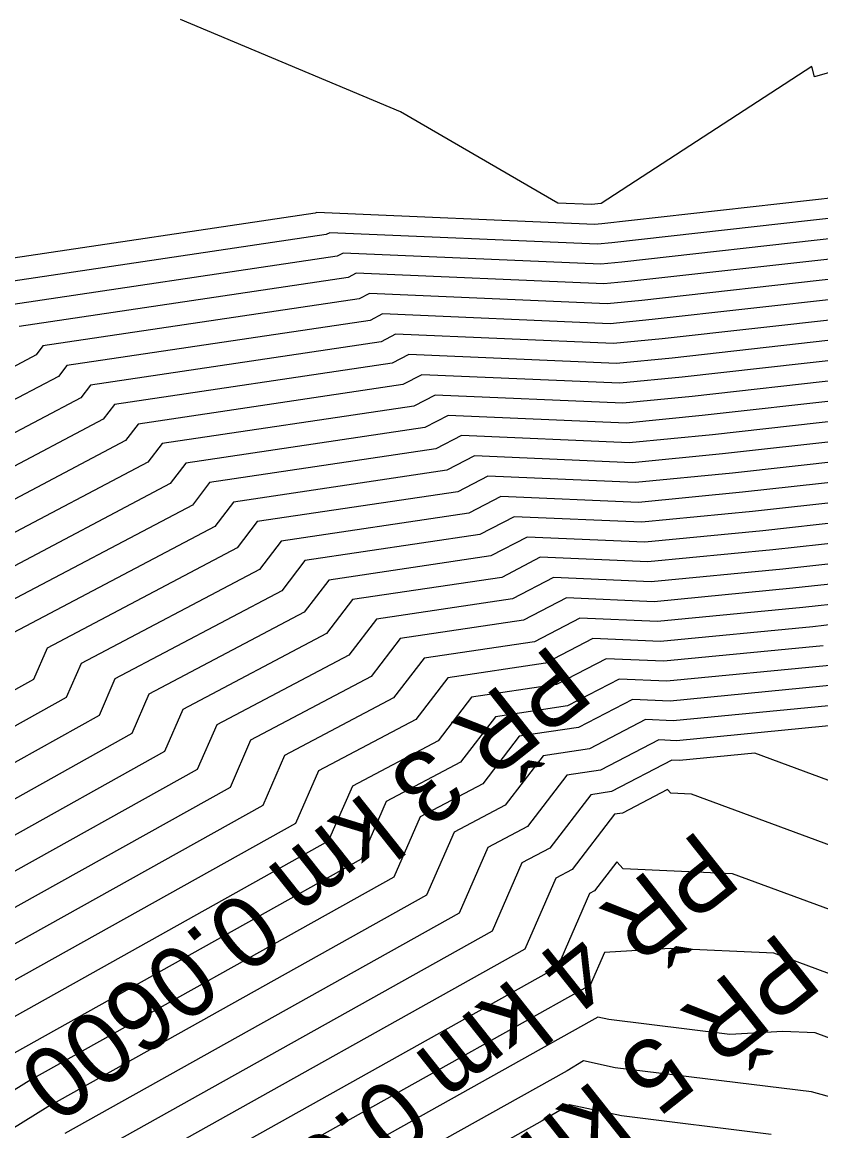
# Model space of a CAD drawing. Extents: x -549394 to -546608, y -1037055 to -1033629.
# Drawn here: x -547230.9 to -547129.8, y -1036014.3 to -1035874.2 of the extents above; entities that cross this region are included whole.
import ezdxf

# ---------------------------------------------------------------- set-up
doc = ezdxf.new("R2010")
doc.units = 0
for name, color, linetype in [('hlavni_vrst', 7, 'Continuous'), ('norm_vrst', 7, 'Continuous'), ('x_popis_pricne_rezy_C411', 7, 'Continuous')]:
    doc.layers.add(name, color=color, linetype=linetype)

msp = doc.modelspace()

# ---------------------------------------------------------------- linework, layer by layer
at = {"layer": 'hlavni_vrst'}
for p, q in [((-547127.29, -1035901.39), (-547155.01, -1035904.49)), ((-547190.28, -1035903.35), (-547191.02, -1035903.73)), ((-547157.67, -1035904.75), (-547190.28, -1035903.35)), ((-547191.02, -1035903.73), (-547234.27, -1035910.17)), ((-547155.01, -1035904.49), (-547157.67, -1035904.75)), ((-547126.73, -1035914.17), (-547148.65, -1035916.62)), ((-547181.96, -1035916.17), (-547184.08, -1035917.28)), ((-547155.68, -1035917.31), (-547181.96, -1035916.17)), ((-547184.08, -1035917.28), (-547219.2, -1035922.5)), ((-547148.65, -1035916.62), (-547155.68, -1035917.31)), ((-547219.2, -1035922.5), (-547220.63, -1035924.36)), ((-547220.63, -1035924.36), (-547253.44, -1035941.66)), ((-547126.18, -1035926.95), (-547142.28, -1035928.75)), ((-547142.28, -1035928.75), (-547153.69, -1035929.86)), ((-547173.64, -1035929), (-547177.14, -1035930.82)), ((-547153.69, -1035929.86), (-547173.64, -1035929)), ((-547177.14, -1035930.82), (-547204.14, -1035934.84)), ((-547204.14, -1035934.84), (-547206.51, -1035937.92)), ((-547206.51, -1035937.92), (-547231.99, -1035951.36)), ((-547125.62, -1035939.73), (-547135.92, -1035940.88)), ((-547135.92, -1035940.88), (-547151.7, -1035942.41)), ((-547165.33, -1035941.82), (-547170.2, -1035944.36)), ((-547151.7, -1035942.41), (-547165.33, -1035941.82)), ((-547170.2, -1035944.36), (-547189.07, -1035947.17)), ((-547189.07, -1035947.17), (-547192.38, -1035951.47)), ((-547192.38, -1035951.47), (-547210.55, -1035961.05)), ((-547129.56, -1035953.01), (-547149.71, -1035954.96)), ((-547157.01, -1035954.65), (-547163.26, -1035957.91)), ((-547149.71, -1035954.96), (-547157.01, -1035954.65)), ((-547163.26, -1035957.91), (-547174.01, -1035959.5)), ((-547174.01, -1035959.5), (-547178.25, -1035965.02)), ((-547210.55, -1035961.05), (-547212.86, -1035966.36)), ((-547178.25, -1035965.02), (-547189.1, -1035970.74)), ((-547212.86, -1035966.36), (-547244.68, -1035984.12)), ((-547138.18, -1035966.59), (-547147.72, -1035967.52)), ((-547125.35, -1035971.32), (-547138.18, -1035966.59)), ((-547148.69, -1035967.47), (-547156.32, -1035971.45)), ((-547147.72, -1035967.52), (-547148.69, -1035967.47)), ((-547189.1, -1035970.74), (-547192.14, -1035977.73)), ((-547158.94, -1035971.84), (-547164.13, -1035978.58)), ((-547156.32, -1035971.45), (-547158.94, -1035971.84)), ((-547192.14, -1035977.73), (-547234.02, -1036001.1)), ((-547164.13, -1035978.58), (-547167.66, -1035980.44)), ((-547167.66, -1035980.44), (-547171.43, -1035989.1)), ((-547171.43, -1035989.1), (-547223.36, -1036018.08)), ((-547159.85, -1036005.5), (-547161.94, -1036006.74)), ((-547155.86, -1036006.35), (-547159.85, -1036005.5)), ((-547161.94, -1036006.74), (-547212.7, -1036035.07)), ((-547131.02, -1036009.42), (-547155.86, -1036006.35)), ((-547127.83, -1036010.31), (-547131.02, -1036009.42))]:
    msp.add_line(p, q, dxfattribs=at)
at = {"layer": 'norm_vrst'}
for p, q in [((-547183, -1035885.49), (-547210.83, -1035873.81)), ((-547112.7, -1035876), (-547130.65, -1035881.06)), ((-547130.98, -1035879.77), (-547157.61, -1035897.08)), ((-547130.65, -1035881.06), (-547130.98, -1035879.77)), ((-547163.1, -1035897.04), (-547183, -1035885.49)), ((-547127.51, -1035896.28), (-547157.56, -1035899.64)), ((-547158.86, -1035897.22), (-547163.1, -1035897.04)), ((-547158.83, -1035897.22), (-547158.86, -1035897.22)), ((-547157.61, -1035897.08), (-547158.83, -1035897.22)), ((-547193.8, -1035898.32), (-547240.29, -1035905.23)), ((-547193.61, -1035898.22), (-547193.8, -1035898.32)), ((-547158.47, -1035899.73), (-547193.61, -1035898.22)), ((-547127.4, -1035898.83), (-547156.28, -1035902.07)), ((-547157.56, -1035899.64), (-547158.47, -1035899.73)), ((-547192.41, -1035901.02), (-547237.28, -1035907.7)), ((-547191.94, -1035900.78), (-547192.41, -1035901.02)), ((-547158.07, -1035902.24), (-547191.94, -1035900.78)), ((-547156.28, -1035902.07), (-547158.07, -1035902.24)), ((-547127.18, -1035903.95), (-547153.74, -1035906.92)), ((-547188.62, -1035905.91), (-547189.63, -1035906.44)), ((-547157.27, -1035907.26), (-547188.62, -1035905.91)), ((-547189.63, -1035906.44), (-547231.25, -1035912.63)), ((-547153.74, -1035906.92), (-547157.27, -1035907.26)), ((-547127.07, -1035906.5), (-547152.47, -1035909.35)), ((-547188.25, -1035909.15), (-547228.24, -1035915.1)), ((-547186.95, -1035908.48), (-547188.25, -1035909.15)), ((-547156.87, -1035909.77), (-547186.95, -1035908.48)), ((-547126.96, -1035909.06), (-547151.19, -1035911.77)), ((-547152.47, -1035909.35), (-547156.87, -1035909.77)), ((-547186.86, -1035911.86), (-547225.23, -1035917.57)), ((-547185.29, -1035911.04), (-547186.86, -1035911.86)), ((-547156.48, -1035912.28), (-547185.29, -1035911.04)), ((-547151.19, -1035911.77), (-547156.48, -1035912.28)), ((-547126.85, -1035911.61), (-547149.92, -1035914.2)), ((-547185.47, -1035914.57), (-547222.21, -1035920.04)), ((-547183.62, -1035913.61), (-547185.47, -1035914.57)), ((-547156.08, -1035914.79), (-547183.62, -1035913.61)), ((-547149.92, -1035914.2), (-547156.08, -1035914.79)), ((-547228.24, -1035915.1), (-547229.11, -1035916.23)), ((-547229.11, -1035916.23), (-547266.3, -1035935.85)), ((-547225.23, -1035917.57), (-547226.28, -1035918.94)), ((-547126.62, -1035916.73), (-547147.37, -1035919.05)), ((-547226.28, -1035918.94), (-547262.02, -1035937.79)), ((-547180.3, -1035918.74), (-547182.7, -1035919.99)), ((-547155.28, -1035919.82), (-547180.3, -1035918.74)), ((-547222.21, -1035920.04), (-547223.46, -1035921.65)), ((-547182.7, -1035919.99), (-547216.19, -1035924.97)), ((-547147.37, -1035919.05), (-547155.28, -1035919.82)), ((-547126.51, -1035919.28), (-547146.1, -1035921.48)), ((-547223.46, -1035921.65), (-547257.73, -1035939.72)), ((-547178.63, -1035921.3), (-547181.31, -1035922.69)), ((-547154.88, -1035922.33), (-547178.63, -1035921.3)), ((-547146.1, -1035921.48), (-547154.88, -1035922.33)), ((-547181.31, -1035922.69), (-547213.17, -1035927.44)), ((-547126.4, -1035921.84), (-547144.83, -1035923.9)), ((-547176.97, -1035923.87), (-547179.92, -1035925.4)), ((-547154.48, -1035924.84), (-547176.97, -1035923.87)), ((-547144.83, -1035923.9), (-547154.48, -1035924.84)), ((-547126.29, -1035924.39), (-547143.56, -1035926.33)), ((-547216.19, -1035924.97), (-547217.81, -1035927.07)), ((-547179.92, -1035925.4), (-547210.16, -1035929.9)), ((-547217.81, -1035927.07), (-547249.15, -1035943.6)), ((-547175.31, -1035926.43), (-547178.53, -1035928.11)), ((-547154.09, -1035927.35), (-547175.31, -1035926.43)), ((-547143.56, -1035926.33), (-547154.09, -1035927.35)), ((-547213.17, -1035927.44), (-547214.98, -1035929.78)), ((-547178.53, -1035928.11), (-547207.15, -1035932.37)), ((-547214.98, -1035929.78), (-547244.86, -1035945.54)), ((-547210.16, -1035929.9), (-547212.16, -1035932.49)), ((-547126.06, -1035929.51), (-547141.01, -1035931.18)), ((-547171.98, -1035931.56), (-547175.76, -1035933.53)), ((-547153.29, -1035932.37), (-547171.98, -1035931.56)), ((-547141.01, -1035931.18), (-547153.29, -1035932.37)), ((-547212.16, -1035932.49), (-547240.57, -1035947.48)), ((-547207.15, -1035932.37), (-547209.33, -1035935.21)), ((-547125.95, -1035932.06), (-547139.74, -1035933.6)), ((-547175.76, -1035933.53), (-547201.12, -1035937.3)), ((-547170.32, -1035934.13), (-547174.37, -1035936.24)), ((-547152.89, -1035934.88), (-547170.32, -1035934.13)), ((-547139.74, -1035933.6), (-547152.89, -1035934.88)), ((-547209.33, -1035935.21), (-547236.28, -1035949.42)), ((-547125.84, -1035934.62), (-547138.46, -1035936.03)), ((-547174.37, -1035936.24), (-547198.11, -1035939.77)), ((-547168.65, -1035936.69), (-547172.98, -1035938.95)), ((-547152.49, -1035937.39), (-547168.65, -1035936.69)), ((-547138.46, -1035936.03), (-547152.49, -1035937.39)), ((-547125.73, -1035937.17), (-547137.19, -1035938.46)), ((-547201.12, -1035937.3), (-547203.68, -1035940.63)), ((-547137.19, -1035938.46), (-547152.1, -1035939.9)), ((-547198.11, -1035939.77), (-547200.86, -1035943.34)), ((-547172.98, -1035938.95), (-547195.1, -1035942.24)), ((-547166.99, -1035939.26), (-547171.59, -1035941.65)), ((-547152.1, -1035939.9), (-547166.99, -1035939.26)), ((-547203.68, -1035940.63), (-547227.7, -1035953.3)), ((-547195.1, -1035942.24), (-547198.03, -1035946.05)), ((-547171.59, -1035941.65), (-547192.08, -1035944.7)), ((-547125.51, -1035942.28), (-547134.65, -1035943.31)), ((-547200.86, -1035943.34), (-547223.41, -1035955.23)), ((-547134.65, -1035943.31), (-547151.3, -1035944.92)), ((-547192.08, -1035944.7), (-547195.21, -1035948.76)), ((-547163.66, -1035944.39), (-547168.82, -1035947.07)), ((-547151.3, -1035944.92), (-547163.66, -1035944.39)), ((-547125.4, -1035944.84), (-547133.37, -1035945.73)), ((-547198.03, -1035946.05), (-547219.13, -1035957.17)), ((-547162, -1035946.95), (-547167.43, -1035949.78)), ((-547150.9, -1035947.43), (-547162, -1035946.95)), ((-547133.37, -1035945.73), (-547150.9, -1035947.43)), ((-547168.82, -1035947.07), (-547186.06, -1035949.64)), ((-547132.1, -1035948.16), (-547150.5, -1035949.94)), ((-547125.28, -1035947.4), (-547132.1, -1035948.16)), ((-547195.21, -1035948.76), (-547214.84, -1035959.11)), ((-547186.06, -1035949.64), (-547189.56, -1035954.18)), ((-547167.43, -1035949.78), (-547183.04, -1035952.1)), ((-547160.34, -1035949.52), (-547166.04, -1035952.49)), ((-547150.5, -1035949.94), (-547160.34, -1035949.52)), ((-547130.83, -1035950.59), (-547150.11, -1035952.45)), ((-547125.17, -1035949.95), (-547130.83, -1035950.59)), ((-547183.04, -1035952.1), (-547186.73, -1035956.89)), ((-547166.04, -1035952.49), (-547180.03, -1035954.57)), ((-547158.67, -1035952.08), (-547164.65, -1035955.2)), ((-547150.11, -1035952.45), (-547158.67, -1035952.08)), ((-547227.7, -1035953.3), (-547229.43, -1035957.26)), ((-547223.41, -1035955.23), (-547225.29, -1035959.54)), ((-547189.56, -1035954.18), (-547206.26, -1035962.99)), ((-547180.03, -1035954.57), (-547183.91, -1035959.6)), ((-547164.65, -1035955.2), (-547177.02, -1035957.04)), ((-547128.28, -1035955.44), (-547149.31, -1035957.47)), ((-547229.43, -1035957.26), (-547253.2, -1035970.53)), ((-547219.13, -1035957.17), (-547221.14, -1035961.81)), ((-547186.73, -1035956.89), (-547201.97, -1035964.93)), ((-547177.02, -1035957.04), (-547181.08, -1035962.31)), ((-547155.34, -1035957.21), (-547161.88, -1035960.61)), ((-547149.31, -1035957.47), (-547155.34, -1035957.21)), ((-547127.01, -1035957.86), (-547148.91, -1035959.99)), ((-547225.29, -1035959.54), (-547251.07, -1035973.93)), ((-547214.84, -1035959.11), (-547217, -1035964.08)), ((-547183.91, -1035959.6), (-547197.68, -1035966.87)), ((-547161.88, -1035960.61), (-547170.99, -1035961.97)), ((-547153.68, -1035959.78), (-547160.49, -1035963.32)), ((-547148.91, -1035959.99), (-547153.68, -1035959.78)), ((-547125.74, -1035960.29), (-547148.51, -1035962.5)), ((-547221.14, -1035961.81), (-547248.94, -1035977.32)), ((-547181.08, -1035962.31), (-547193.39, -1035968.81)), ((-547170.99, -1035961.97), (-547175.43, -1035967.73)), ((-547152.02, -1035962.34), (-547159.1, -1035966.03)), ((-547148.51, -1035962.5), (-547152.02, -1035962.34)), ((-547206.26, -1035962.99), (-547208.71, -1035968.63)), ((-547160.49, -1035963.32), (-547167.98, -1035964.44)), ((-547126.19, -1035962.88), (-547148.11, -1035965.01)), ((-547217, -1035964.08), (-547246.81, -1035980.72)), ((-547201.97, -1035964.93), (-547204.57, -1035970.91)), ((-547167.98, -1035964.44), (-547172.6, -1035970.45)), ((-547150.35, -1035964.91), (-547157.71, -1035968.74)), ((-547148.11, -1035965.01), (-547150.35, -1035964.91)), ((-547159.1, -1035966.03), (-547164.97, -1035966.9)), ((-547197.68, -1035966.87), (-547200.43, -1035973.18)), ((-547175.43, -1035967.73), (-547184.81, -1035972.68)), ((-547164.97, -1035966.9), (-547169.78, -1035973.16)), ((-547208.71, -1035968.63), (-547242.55, -1035987.51)), ((-547193.39, -1035968.81), (-547196.28, -1035975.46)), ((-547161.95, -1035969.37), (-547166.95, -1035975.87)), ((-547157.71, -1035968.74), (-547161.95, -1035969.37)), ((-547172.6, -1035970.45), (-547180.52, -1035974.62)), ((-547204.57, -1035970.91), (-547240.42, -1035990.91)), ((-547149.24, -1035971.19), (-547154.94, -1035974.16)), ((-547148.8, -1035971.65), (-547149.24, -1035971.19)), ((-547146.21, -1035971.76), (-547148.8, -1035971.65)), ((-547126, -1035979.22), (-547146.21, -1035971.76)), ((-547200.43, -1035973.18), (-547238.28, -1035994.31)), ((-547184.81, -1035972.68), (-547188, -1035980)), ((-547169.78, -1035973.16), (-547176.23, -1035976.56)), ((-547180.52, -1035974.62), (-547183.85, -1035982.28)), ((-547155.93, -1035974.31), (-547161.3, -1035981.29)), ((-547154.94, -1035974.16), (-547155.93, -1035974.31)), ((-547196.28, -1035975.46), (-547236.15, -1035997.7)), ((-547166.95, -1035975.87), (-547171.95, -1035978.5)), ((-547176.23, -1035976.56), (-547179.71, -1035984.55)), ((-547171.95, -1035978.5), (-547175.57, -1035986.83)), ((-547188, -1035980), (-547231.89, -1036004.5)), ((-547155.66, -1035980.34), (-547158.48, -1035984)), ((-547154.84, -1035981.2), (-547155.66, -1035980.34)), ((-547161.3, -1035981.29), (-547163.37, -1035982.38)), ((-547140.99, -1035981.82), (-547154.84, -1035981.2)), ((-547126.64, -1035987.12), (-547140.99, -1035981.82)), ((-547183.85, -1035982.28), (-547229.76, -1036007.89)), ((-547163.37, -1035982.38), (-547167.28, -1035991.38)), ((-547179.71, -1035984.55), (-547227.63, -1036011.29)), ((-547159.08, -1035984.32), (-547163.14, -1035993.65)), ((-547158.48, -1035984), (-547159.08, -1035984.32)), ((-547175.57, -1035986.83), (-547225.49, -1036014.69)), ((-547167.28, -1035991.38), (-547221.23, -1036021.48)), ((-547157.19, -1035991.77), (-547159, -1035995.92)), ((-547148.9, -1035991.29), (-547157.19, -1035991.77)), ((-547135.78, -1035991.88), (-547148.9, -1035991.29)), ((-547127.28, -1035995.02), (-547135.78, -1035991.88)), ((-547163.14, -1035993.65), (-547219.1, -1036024.88)), ((-547159, -1035995.92), (-547216.97, -1036028.27)), ((-547158.06, -1035999.96), (-547158.79, -1036000.4)), ((-547156.66, -1036000.26), (-547158.06, -1035999.96)), ((-547141.34, -1036002.15), (-547156.66, -1036000.26)), ((-547158.79, -1036000.4), (-547214.84, -1036031.67)), ((-547134.63, -1036001.76), (-547141.34, -1036002.15)), ((-547130.56, -1036001.94), (-547134.63, -1036001.76)), ((-547127.92, -1036002.92), (-547130.56, -1036001.94)), ((-547229.76, -1036007.89), (-547234.25, -1036010.67)), ((-547227.63, -1036011.29), (-547232.32, -1036014.19)), ((-547161.65, -1036011.04), (-547165.09, -1036013.08)), ((-547155.06, -1036012.44), (-547161.65, -1036011.04)), ((-547136.12, -1036014.78), (-547155.06, -1036012.44)), ((-547165.09, -1036013.08), (-547210.57, -1036038.46))]:
    msp.add_line(p, q, dxfattribs=at)

# ---------------------------------------------------------------- texts
at = {"layer": 'x_popis_pricne_rezy_C411'}
for s, p in [('PŘ 3 km 0.0600', (-547163.9, -1035952.56)), ('PŘ 4 km 0.0900', (-547145.23, -1035976.05)), ('PŘ 5 km 0.0947', (-547134.98, -1035988.95))]:
    msp.add_text(s, height=9.0627, rotation=218.4742, dxfattribs=at).set_placement(p)

doc.saveas('drawing.dxf')
